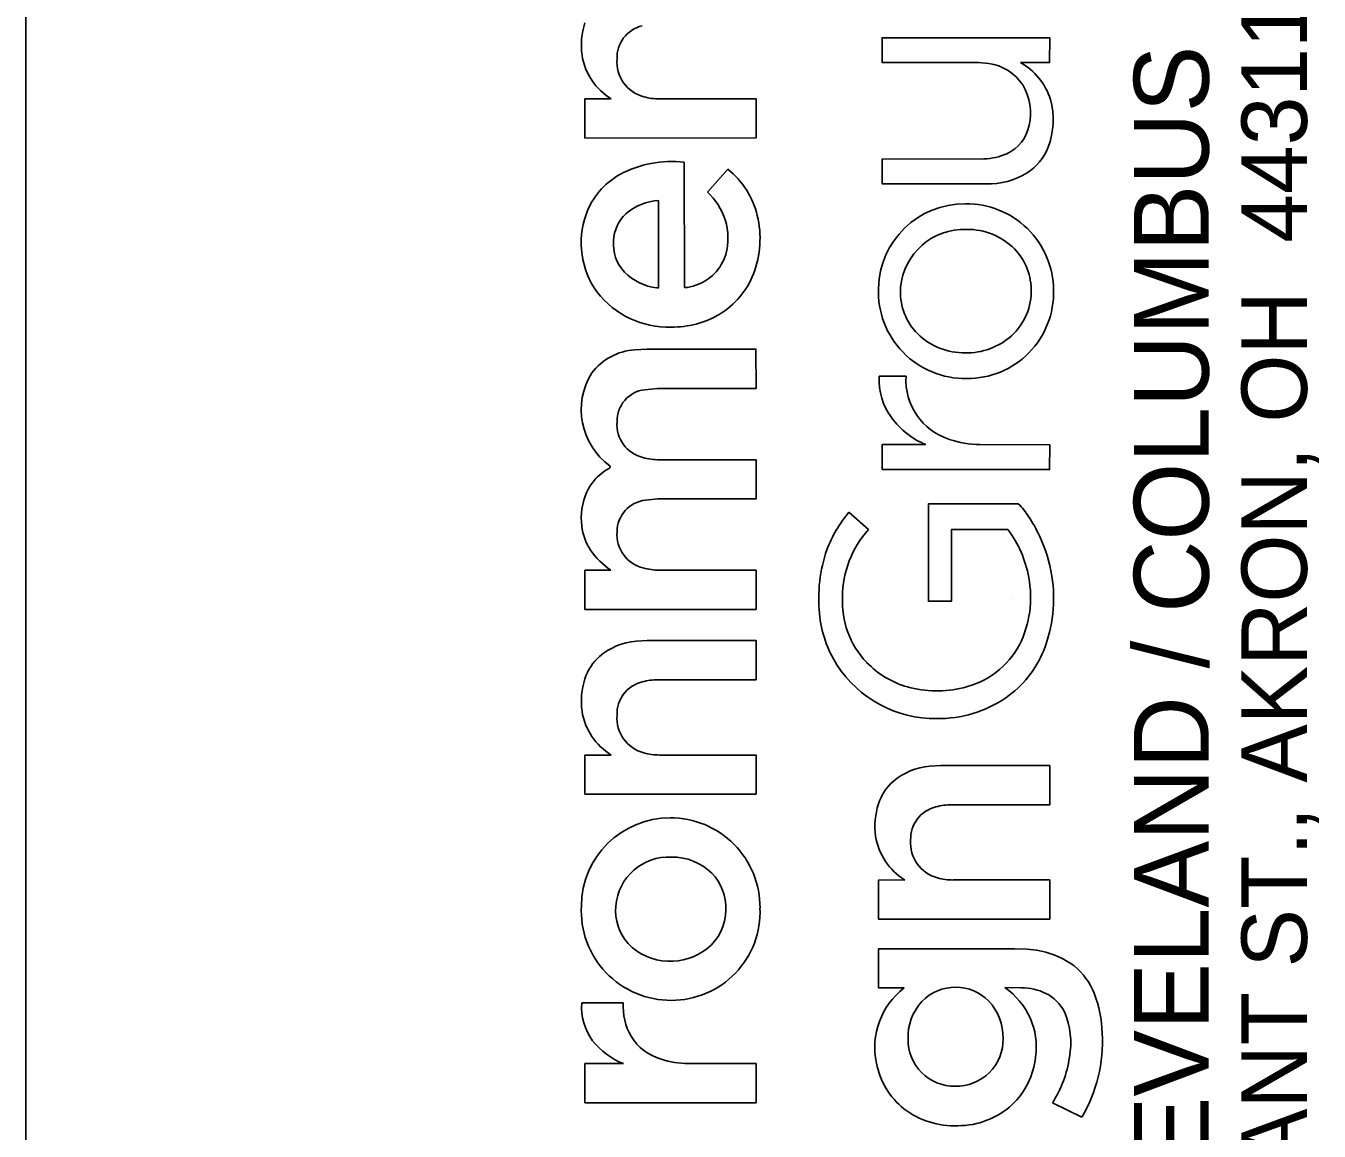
# Model space of a CAD drawing. Extents: x -6.7 to 34, y -1.6 to 22.
# Drawn here: x 32 to 32.984, y 3.594 to 4.436 of the extents above; entities that cross this region are included whole.
import ezdxf

# ---------------------------------------------------------------- set-up
doc = ezdxf.new("R2010")
doc.units = 0
doc.layers.add('SH_Border', color=7, linetype='Continuous')
doc.layers.add('SH_Cut_Line', color=7, linetype='Continuous')

msp = doc.modelspace()

# ---------------------------------------------------------------- linework, layer by layer
at = {"layer": 'SH_Border'}
msp.add_line((32, 0.5), (32, 21.5), dxfattribs=at)
at = {"layer": 'SH_Cut_Line'}
for p, q in [((32.65152, 4.40801), (32.65153, 4.42672)), ((32.65153, 4.42672), (32.7791, 4.42664)), ((32.7791, 4.42664), (32.77908, 4.40796)), ((32.7249, 4.40796), (32.65152, 4.40801)), ((32.7328, 4.40727), (32.7249, 4.40796)), ((32.77908, 4.40796), (32.75689, 4.40796)), ((32.42542, 4.38016), (32.44552, 4.38021)), ((32.42542, 4.35035), (32.42542, 4.38016)), ((32.48222, 4.38021), (32.55569, 4.38021)), ((32.55569, 4.38021), (32.55571, 4.35045)), ((32.55571, 4.35045), (32.42542, 4.35035)), ((32.50108, 4.33209), (32.50118, 4.23657)), ((32.65154, 4.33443), (32.72905, 4.3345)), ((32.65165, 4.31543), (32.65154, 4.33443)), ((32.51882, 4.30927), (32.53422, 4.32662)), ((32.73073, 4.31543), (32.65165, 4.31543)), ((32.48144, 4.23644), (32.48144, 4.30296)), ((32.48016, 4.23628), (32.48144, 4.23644)), ((32.46329, 4.18915), (32.47259, 4.18968)), ((32.47259, 4.18968), (32.55557, 4.18968)), ((32.55557, 4.18968), (32.55571, 4.15982)), ((32.64932, 4.16907), (32.66978, 4.16907)), ((32.48058, 4.15981), (32.47102, 4.15881)), ((32.55571, 4.15982), (32.48058, 4.15981)), ((32.65152, 4.11699), (32.68476, 4.117)), ((32.65152, 4.098), (32.65152, 4.11699)), ((32.72605, 4.11703), (32.7791, 4.11696)), ((32.7791, 4.11696), (32.77903, 4.098)), ((32.48218, 4.10553), (32.55571, 4.10548)), ((32.55571, 4.10548), (32.55571, 4.07568)), ((32.44443, 4.09922), (32.44455, 4.10072)), ((32.77903, 4.098), (32.65152, 4.098)), ((32.4809, 4.07567), (32.47143, 4.07474)), ((32.55571, 4.07568), (32.4809, 4.07567)), ((32.62636, 4.06548), (32.64114, 4.05241)), ((32.6868, 4.07185), (32.75516, 4.07192)), ((32.6868, 3.99778), (32.6868, 4.07185)), ((32.70448, 4.05241), (32.70432, 3.99775)), ((32.74737, 4.05227), (32.70448, 4.05241)), ((32.42542, 3.99152), (32.42545, 4.02138)), ((32.42545, 4.02138), (32.44515, 4.02138)), ((32.48206, 4.02138), (32.55571, 4.02136)), ((32.55571, 4.02136), (32.55571, 3.99156)), ((32.70432, 3.99775), (32.6868, 3.99778)), ((32.75, 4), (32.75, 4)), ((32.55571, 3.99156), (32.42542, 3.99152)), ((32.46439, 3.96736), (32.47289, 3.96783)), ((32.47289, 3.96783), (32.55571, 3.96783)), ((32.55571, 3.96783), (32.55571, 3.93804)), ((32.55571, 3.93804), (32.4814, 3.93796)), ((32.42542, 3.88066), (32.44552, 3.88071)), ((32.42542, 3.85086), (32.42542, 3.88066)), ((32.48222, 3.88071), (32.55569, 3.88071)), ((32.55569, 3.88071), (32.55571, 3.85096)), ((32.68784, 3.8722), (32.69634, 3.87266)), ((32.69634, 3.87266), (32.77916, 3.87266)), ((32.77916, 3.87266), (32.77917, 3.84287)), ((32.55571, 3.85096), (32.42542, 3.85086)), ((32.77917, 3.84287), (32.70485, 3.8428)), ((32.64888, 3.7855), (32.66897, 3.78555)), ((32.64888, 3.75569), (32.64888, 3.7855)), ((32.70568, 3.78555), (32.77915, 3.78555)), ((32.77915, 3.78555), (32.77917, 3.75579)), ((32.77917, 3.75579), (32.64888, 3.75569)), ((32.6489, 3.70336), (32.64889, 3.73322)), ((32.64889, 3.73322), (32.75236, 3.73322)), ((32.75236, 3.73322), (32.76191, 3.73285)), ((32.66836, 3.70336), (32.6489, 3.70336)), ((32.75763, 3.70356), (32.74487, 3.70361)), ((32.42299, 3.69193), (32.45454, 3.69193)), ((32.42542, 3.64577), (32.45473, 3.64579)), ((32.42542, 3.61593), (32.42542, 3.64577)), ((32.50413, 3.64581), (32.55571, 3.64573)), ((32.55571, 3.64573), (32.55565, 3.61593)), ((32.55565, 3.61593), (32.42542, 3.61593)), ((32.8036, 3.60491), (32.7812, 3.61598))]:
    msp.add_line(p, q, dxfattribs=at)
for points in [[(32.7328, 4.40727), (32.7249, 4.40796), (32.65152, 4.40801), (32.65153, 4.42672), (32.7791, 4.42664), (32.77908, 4.40796), (32.75689, 4.40796)], [(32.42542, 4.35035), (32.42542, 4.38016), (32.44552, 4.38021)], [(32.48222, 4.38021), (32.55569, 4.38021), (32.55571, 4.35045), (32.42542, 4.35035)], [(32.50108, 4.33209), (32.50118, 4.23657)], [(32.73073, 4.31543), (32.65165, 4.31543), (32.65154, 4.33443), (32.72905, 4.3345)], [(32.51882, 4.30927), (32.53422, 4.32662)], [(32.48016, 4.23628), (32.48144, 4.23644), (32.48144, 4.30296)], [(32.46329, 4.18915), (32.47259, 4.18968), (32.55557, 4.18968), (32.55571, 4.15982), (32.48058, 4.15981), (32.47102, 4.15881)], [(32.64932, 4.16907), (32.66978, 4.16907)], [(32.72605, 4.11703), (32.7791, 4.11696), (32.77903, 4.098), (32.65152, 4.098)], [(32.65152, 4.098), (32.65152, 4.11699), (32.68476, 4.117)], [(32.48218, 4.10553), (32.55571, 4.10548), (32.55571, 4.07568), (32.4809, 4.07567), (32.47143, 4.07474)], [(32.44443, 4.09922), (32.44455, 4.10072)], [(32.62636, 4.06548), (32.64114, 4.05241)], [(32.74737, 4.05227), (32.70448, 4.05241), (32.70432, 3.99775), (32.6868, 3.99778), (32.6868, 4.07185), (32.75516, 4.07192)], [(32.42542, 3.99152), (32.42545, 4.02138), (32.44515, 4.02138)], [(32.48206, 4.02138), (32.55571, 4.02136), (32.55571, 3.99156), (32.42542, 3.99152)], [(32.46439, 3.96736), (32.47289, 3.96783), (32.55571, 3.96783), (32.55571, 3.93804), (32.4814, 3.93796)], [(32.42542, 3.85086), (32.42542, 3.88066), (32.44552, 3.88071)], [(32.48222, 3.88071), (32.55569, 3.88071), (32.55571, 3.85096), (32.42542, 3.85086)], [(32.68784, 3.8722), (32.69634, 3.87266), (32.77916, 3.87266), (32.77917, 3.84287), (32.70485, 3.8428)], [(32.64888, 3.75569), (32.64888, 3.7855), (32.66897, 3.78555)], [(32.70568, 3.78555), (32.77915, 3.78555), (32.77917, 3.75579), (32.64888, 3.75569)], [(32.66836, 3.70336), (32.6489, 3.70336), (32.64889, 3.73322), (32.75236, 3.73322), (32.76191, 3.73285)], [(32.75763, 3.70356), (32.74487, 3.70361)], [(32.42299, 3.69193), (32.45454, 3.69193)], [(32.50413, 3.64581), (32.55571, 3.64573), (32.55565, 3.61593), (32.42542, 3.61593)], [(32.42542, 3.61593), (32.42542, 3.64577), (32.45473, 3.64579)], [(32.8036, 3.60491), (32.7812, 3.61598)]]:
    msp.add_lwpolyline(points, dxfattribs=at)
for centre, radius, start, end in [((32.47872, 4.42108), 0.05602, 162.27398, 187.79173), ((32.47872, 4.42108), 0.05602, 162.27398, 187.79173), ((32.47482, 4.41155), 0.02498, 103.68683, 182.21395), ((32.47482, 4.41155), 0.02498, 103.68683, 182.21395), ((32.47027, 4.4209), 0.04763, 188.96462, 238.69865), ((32.47027, 4.4209), 0.04763, 188.96462, 238.69865), ((32.47735, 4.40846), 0.02757, 175.58441, 255.13816), ((32.47735, 4.40846), 0.02757, 175.58441, 255.13816), ((32.72711, 4.36998), 0.03772, 33.50082, 81.32954), ((32.72711, 4.36998), 0.03772, 33.50082, 81.32954), ((32.73239, 4.36485), 0.04959, 17.62209, 60.38974), ((32.73239, 4.36485), 0.04959, 17.62209, 60.38974), ((32.72414, 4.3695), 0.04048, 346.56179, 31.75389), ((32.72414, 4.3695), 0.04048, 346.56179, 31.75389), ((32.48183, 4.42235), 0.04215, 254.08913, 270.52838), ((32.48183, 4.42235), 0.04215, 254.08913, 270.52838), ((32.72343, 4.36415), 0.05838, 339.16197, 15.61485), ((32.72343, 4.36415), 0.05838, 339.16197, 15.61485), ((32.73371, 4.36616), 0.03042, 294.63214, 348.48625), ((32.73371, 4.36616), 0.03042, 294.63214, 348.48625), ((32.739, 4.35901), 0.04201, 303.10391, 338.15613), ((32.739, 4.35901), 0.04201, 303.10391, 338.15613), ((32.49176, 4.24874), 0.08387, 83.62118, 118.28448), ((32.49176, 4.24874), 0.08387, 83.62118, 118.28448), ((32.72747, 4.38081), 0.04633, 271.95199, 294.08943), ((32.72747, 4.38081), 0.04633, 271.95199, 294.08943), ((32.47894, 4.27368), 0.05583, 118.82935, 160.62242), ((32.47894, 4.27368), 0.05583, 118.82935, 160.62242), ((32.49399, 4.2763), 0.06443, 13.53275, 51.36266), ((32.49399, 4.2763), 0.06443, 13.53275, 51.36266), ((32.7321, 4.37256), 0.05715, 268.62699, 301.47779), ((32.7321, 4.37256), 0.05715, 268.62699, 301.47779), ((32.4844, 4.26071), 0.04236, 94.01311, 130.88062), ((32.4844, 4.26071), 0.04236, 94.01311, 130.88062), ((32.48033, 4.27018), 0.05485, 19.0387, 45.44322), ((32.48033, 4.27018), 0.05485, 19.0387, 45.44322), ((32.48697, 4.27074), 0.06438, 160.52138, 215.78155), ((32.48697, 4.27074), 0.06438, 160.52138, 215.78155), ((32.47703, 4.2709), 0.02985, 132.98553, 177.1802), ((32.47703, 4.2709), 0.02985, 132.98553, 177.1802), ((32.48289, 4.27384), 0.0758, 339.35431, 13.37708), ((32.48289, 4.27384), 0.0758, 339.35431, 13.37708), ((32.71435, 4.23484), 0.06552, 89.48213, 178.77752), ((32.71435, 4.23484), 0.06552, 89.48213, 178.77752), ((32.71582, 4.23414), 0.06623, 0.42265, 90.7613), ((32.71582, 4.23414), 0.06623, 0.42265, 90.7613), ((32.48724, 4.27433), 0.04701, 344.60723, 17.00675), ((32.48724, 4.27433), 0.04701, 344.60723, 17.00675), ((32.47824, 4.26966), 0.03114, 175.00138, 223.2876), ((32.47824, 4.26966), 0.03114, 175.00138, 223.2876), ((32.71397, 4.23244), 0.04846, 87.68827, 175.01696), ((32.71397, 4.23244), 0.04846, 87.68827, 175.01696), ((32.71659, 4.23036), 0.05052, 44.91202, 90.75914), ((32.71659, 4.23036), 0.05052, 44.91202, 90.75914), ((32.49895, 4.27177), 0.03504, 288.01084, 343.55364), ((32.49895, 4.27177), 0.03504, 288.01084, 343.55364), ((32.71955, 4.23452), 0.04549, 358.32279, 43.83486), ((32.71955, 4.23452), 0.04549, 358.32279, 43.83486), ((32.48546, 4.27826), 0.04232, 225.06454, 262.79701), ((32.48546, 4.27826), 0.04232, 225.06454, 262.79701), ((32.49548, 4.26982), 0.0626, 300.94393, 338.73223), ((32.49548, 4.26982), 0.0626, 300.94393, 338.73223), ((32.48908, 4.27516), 0.06872, 217.74341, 271.65606), ((32.48908, 4.27516), 0.06872, 217.74341, 271.65606), ((32.50129, 4.25678), 0.02021, 269.70042, 294.87295), ((32.50129, 4.25678), 0.02021, 269.70042, 294.87295), ((32.71483, 4.2334), 0.06606, 177.53728, 270.94524), ((32.71483, 4.2334), 0.06606, 177.53728, 270.94524), ((32.71085, 4.23311), 0.0453, 175.51467, 221.42047), ((32.71085, 4.23311), 0.0453, 175.51467, 221.42047), ((32.71671, 4.23271), 0.06536, 269.30834, 1.67905), ((32.71671, 4.23271), 0.06536, 269.30834, 1.67905), ((32.71931, 4.23374), 0.04572, 308.90382, 359.30947), ((32.71931, 4.23374), 0.04572, 308.90382, 359.30947), ((32.49204, 4.27702), 0.07055, 269.20529, 300.33566), ((32.49204, 4.27702), 0.07055, 269.20529, 300.33566), ((32.71399, 4.23734), 0.05046, 222.66255, 268.37331), ((32.71399, 4.23734), 0.05046, 222.66255, 268.37331), ((32.71567, 4.23859), 0.05178, 266.55312, 308.67253), ((32.71567, 4.23859), 0.05178, 266.55312, 308.67253), ((32.46638, 4.14404), 0.04521, 93.91118, 142.30723), ((32.46638, 4.14404), 0.04521, 93.91118, 142.30723), ((32.47585, 4.14373), 0.05319, 148.28793, 233.9556), ((32.47585, 4.14373), 0.05319, 148.28793, 233.9556), ((32.69878, 4.16662), 0.04952, 177.16211, 216.28024), ((32.69878, 4.16662), 0.04952, 177.16211, 216.28024), ((32.71735, 4.16638), 0.04764, 176.76988, 252.15044), ((32.71735, 4.16638), 0.04764, 176.76988, 252.15044), ((32.47384, 4.13499), 0.02399, 96.75763, 181.6251), ((32.47384, 4.13499), 0.02399, 96.75763, 181.6251), ((32.47577, 4.13241), 0.02597, 175.81573, 256.16716), ((32.47577, 4.13241), 0.02597, 175.81573, 256.16716), ((32.70975, 4.17555), 0.06366, 216.91526, 246.88619), ((32.70975, 4.17555), 0.06366, 216.91526, 246.88619), ((32.7269, 4.19175), 0.07473, 251.13884, 269.34694), ((32.7269, 4.19175), 0.07473, 251.13884, 269.34694), ((32.4817, 4.15053), 0.04501, 254.34629, 270.61033), ((32.4817, 4.15053), 0.04501, 254.34629, 270.61033), ((32.4638, 4.06267), 0.04137, 117.91625, 139.24296), ((32.4638, 4.06267), 0.04137, 117.91625, 139.24296), ((32.46194, 4.06452), 0.03875, 139.52447, 154.84698), ((32.46194, 4.06452), 0.03875, 139.52447, 154.84698), ((32.47144, 4.0612), 0.04877, 156.06382, 187.3493), ((32.47144, 4.0612), 0.04877, 156.06382, 187.3493), ((32.47421, 4.05056), 0.02434, 96.5532, 179.94902), ((32.47421, 4.05056), 0.02434, 96.5532, 179.94902), ((32.70163, 4.00187), 0.09855, 139.79476, 159.13696), ((32.70163, 4.00187), 0.09855, 139.79476, 159.13696), ((32.72498, 4.03937), 0.04438, 30.98913, 47.16099), ((32.72498, 4.03937), 0.04438, 30.98913, 47.16099), ((32.46461, 4.05974), 0.04181, 186.5579, 213.38846), ((32.46461, 4.05974), 0.04181, 186.5579, 213.38846), ((32.67091, 4.00018), 0.11106, 25.30315, 33.96179), ((32.67091, 4.00018), 0.11106, 25.30315, 33.96179), ((32.47608, 4.04863), 0.02628, 175.722, 255.78627), ((32.47608, 4.04863), 0.02628, 175.722, 255.78627), ((32.69899, 4.00079), 0.07753, 138.25804, 179.70064), ((32.69899, 4.00079), 0.07753, 138.25804, 179.70064), ((32.67889, 4.00099), 0.08556, 10.07509, 36.83189), ((32.67889, 4.00099), 0.08556, 10.07509, 36.83189), ((32.6704, 3.99987), 0.11166, 8.80339, 25.33484), ((32.6704, 3.99987), 0.11166, 8.80339, 25.33484), ((32.47886, 4.07078), 0.0598, 214.70433, 235.68724), ((32.47886, 4.07078), 0.0598, 214.70433, 235.68724), ((32.7187, 3.99968), 0.11536, 161.14379, 185.62812), ((32.7187, 3.99968), 0.11536, 161.14379, 185.62812), ((32.48195, 4.06518), 0.0438, 253.66719, 270.14979), ((32.48195, 4.06518), 0.0438, 253.66719, 270.14979), ((32.68425, 4.00057), 0.08036, 333.46689, 11.03668), ((32.68425, 4.00057), 0.08036, 333.46689, 11.03668), ((32.67564, 3.99977), 0.10649, 338.28866, 9.28548), ((32.67564, 3.99977), 0.10649, 338.28866, 9.28548), ((32.68811, 3.99732), 0.06676, 176.66577, 223.6912), ((32.68811, 3.99732), 0.06676, 176.66577, 223.6912), ((32.69336, 3.99699), 0.08987, 185.50773, 212.01294), ((32.69336, 3.99699), 0.08987, 185.50773, 212.01294), ((32.46871, 3.91767), 0.04988, 94.97056, 130.22484), ((32.46871, 3.91767), 0.04988, 94.97056, 130.22484), ((32.69868, 3.99547), 0.0652, 282.88151, 331.81475), ((32.69868, 3.99547), 0.0652, 282.88151, 331.81475), ((32.69835, 3.99168), 0.08241, 305.03061, 337.67573), ((32.69835, 3.99168), 0.08241, 305.03061, 337.67573), ((32.46348, 3.92602), 0.04016, 132.22383, 161.68229), ((32.46348, 3.92602), 0.04016, 132.22383, 161.68229), ((32.69211, 3.99748), 0.08908, 212.70222, 270.71399), ((32.69211, 3.99748), 0.08908, 212.70222, 270.71399), ((32.69045, 4.00011), 0.07039, 224.02147, 253.88), ((32.69045, 4.00011), 0.07039, 224.02147, 253.88), ((32.47872, 3.92158), 0.05602, 162.27398, 187.79173), ((32.47872, 3.92158), 0.05602, 162.27398, 187.79173), ((32.48108, 3.89196), 0.04601, 89.60515, 105.33026), ((32.48108, 3.89196), 0.04601, 89.60515, 105.33026), ((32.47482, 3.91206), 0.02498, 103.68683, 182.21395), ((32.47482, 3.91206), 0.02498, 103.68683, 182.21395), ((32.69318, 4.01254), 0.08309, 254.45353, 283.9512), ((32.69318, 4.01254), 0.08309, 254.45353, 283.9512), ((32.69429, 3.99979), 0.09138, 269.3273, 304.19632), ((32.69429, 3.99979), 0.09138, 269.3273, 304.19632), ((32.47027, 3.92141), 0.04763, 188.96462, 238.69865), ((32.47027, 3.92141), 0.04763, 188.96462, 238.69865), ((32.47735, 3.90897), 0.02757, 175.58441, 255.13816), ((32.47735, 3.90897), 0.02757, 175.58441, 255.13816), ((32.48183, 3.92286), 0.04215, 254.08913, 270.52838), ((32.48183, 3.92286), 0.04215, 254.08913, 270.52838), ((32.69216, 3.82251), 0.04988, 94.97056, 130.22484), ((32.69216, 3.82251), 0.04988, 94.97056, 130.22484), ((32.68694, 3.83085), 0.04016, 132.22383, 161.68229), ((32.68694, 3.83085), 0.04016, 132.22383, 161.68229), ((32.70217, 3.82642), 0.05602, 162.27398, 187.79173), ((32.70217, 3.82642), 0.05602, 162.27398, 187.79173), ((32.69828, 3.81689), 0.02498, 103.68683, 182.21395), ((32.69828, 3.81689), 0.02498, 103.68683, 182.21395), ((32.70453, 3.79679), 0.04601, 89.60515, 105.33026), ((32.70453, 3.79679), 0.04601, 89.60515, 105.33026), ((32.49014, 3.76543), 0.0674, 89.84756, 179.64047), ((32.49014, 3.76543), 0.0674, 89.84756, 179.64047), ((32.49057, 3.76474), 0.0681, 359.54009, 90.21138), ((32.49057, 3.76474), 0.0681, 359.54009, 90.21138), ((32.69372, 3.82624), 0.04763, 188.96462, 238.69865), ((32.69372, 3.82624), 0.04763, 188.96462, 238.69865), ((32.7008, 3.81381), 0.02757, 175.58441, 255.13816), ((32.7008, 3.81381), 0.02757, 175.58441, 255.13816), ((32.48923, 3.76263), 0.0404, 87.04809, 175.57259), ((32.48923, 3.76263), 0.0404, 87.04809, 175.57259), ((32.49204, 3.75999), 0.04299, 45.84264, 90.98008), ((32.49204, 3.75999), 0.04299, 45.84264, 90.98008), ((32.49458, 3.76421), 0.03821, 357.88569, 44.15902), ((32.49458, 3.76421), 0.03821, 357.88569, 44.15902), ((32.70529, 3.82769), 0.04215, 254.08913, 270.52838), ((32.70529, 3.82769), 0.04215, 254.08913, 270.52838), ((32.49083, 3.76209), 0.06819, 176.8344, 270.40384), ((32.49083, 3.76209), 0.06819, 176.8344, 270.40384), ((32.48729, 3.7625), 0.03848, 175.15378, 221.14706), ((32.48729, 3.7625), 0.03848, 175.15378, 221.14706), ((32.49123, 3.76139), 0.06749, 270.06243, 2.37759), ((32.49123, 3.76139), 0.06749, 270.06243, 2.37759), ((32.49446, 3.76318), 0.0383, 308.28936, 359.43468), ((32.49446, 3.76318), 0.0383, 308.28936, 359.43468), ((32.48919, 3.76607), 0.04228, 223.09994, 268.80895), ((32.48919, 3.76607), 0.04228, 223.09994, 268.80895), ((32.49096, 3.7679), 0.04418, 266.56515, 308.06078), ((32.49096, 3.7679), 0.04418, 266.56515, 308.06078), ((32.75907, 3.66789), 0.06503, 53.40344, 87.49062), ((32.75907, 3.66789), 0.06503, 53.40344, 87.49062), ((32.76517, 3.68039), 0.05141, 21.60748, 50.5577), ((32.76517, 3.68039), 0.05141, 21.60748, 50.5577), ((32.70292, 3.65813), 0.05692, 127.37482, 192.22468), ((32.70292, 3.65813), 0.05692, 127.37482, 192.22468), ((32.70693, 3.66927), 0.0346, 88.47302, 136.42562), ((32.70693, 3.66927), 0.0346, 88.47302, 136.42562), ((32.70814, 3.66963), 0.03424, 44.27195, 90.47623), ((32.70814, 3.66963), 0.03424, 44.27195, 90.47623), ((32.71421, 3.65829), 0.05472, 352.1125, 55.92295), ((32.71421, 3.65829), 0.05472, 352.1125, 55.92295), ((32.75666, 3.65725), 0.04633, 65.01687, 88.8011), ((32.75666, 3.65725), 0.04633, 65.01687, 88.8011), ((32.46616, 3.68882), 0.04329, 175.87313, 216.34747), ((32.46616, 3.68882), 0.04329, 175.87313, 216.34747), ((32.50087, 3.68948), 0.04639, 176.9688, 209.60636), ((32.50087, 3.68948), 0.04639, 176.9688, 209.60636), ((32.71141, 3.66602), 0.0401, 137.46739, 182.33237), ((32.71141, 3.66602), 0.0401, 137.46739, 182.33237), ((32.70368, 3.666), 0.03996, 358.57141, 43.53765), ((32.70368, 3.666), 0.03996, 358.57141, 43.53765), ((32.7626, 3.67155), 0.03085, 26.26808, 63.80301), ((32.7626, 3.67155), 0.03085, 26.26808, 63.80301), ((32.73069, 3.66714), 0.08835, 1.15143, 21.3627), ((32.73069, 3.66714), 0.08835, 1.15143, 21.3627), ((32.73565, 3.66154), 0.05953, 349.30734, 23.43071), ((32.73565, 3.66154), 0.05953, 349.30734, 23.43071), ((32.47466, 3.69716), 0.05511, 218.09809, 248.7907), ((32.47466, 3.69716), 0.05511, 218.09809, 248.7907), ((32.49514, 3.68814), 0.04079, 211.94466, 253.2028), ((32.49514, 3.68814), 0.04079, 211.94466, 253.2028), ((32.70645, 3.6637), 0.03511, 178.88208, 271.08374), ((32.70645, 3.6637), 0.03511, 178.88208, 271.08374), ((32.70818, 3.66404), 0.03546, 268.27882, 1.55016), ((32.70818, 3.66404), 0.03546, 268.27882, 1.55016), ((32.70538, 3.66244), 0.11383, 329.6388, 3.25998), ((32.70538, 3.66244), 0.11383, 329.6388, 3.25998), ((32.50465, 3.7165), 0.07069, 252.46555, 269.57296), ((32.50465, 3.7165), 0.07069, 252.46555, 269.57296), ((32.70463, 3.65696), 0.05837, 190.75182, 231.28919), ((32.70463, 3.65696), 0.05837, 190.75182, 231.28919), ((32.70988, 3.65708), 0.05887, 313.74196, 353.8554), ((32.70988, 3.65708), 0.05887, 313.74196, 353.8554), ((32.70738, 3.66334), 0.08771, 327.31495, 351.57478), ((32.70738, 3.66334), 0.08771, 327.31495, 351.57478), ((32.70954, 3.65901), 0.06051, 269.6361, 312.70877), ((32.70954, 3.65901), 0.06051, 269.6361, 312.70877), ((32.70632, 3.66112), 0.06269, 232.46061, 272.59022), ((32.70632, 3.66112), 0.06269, 232.46061, 272.59022)]:
    msp.add_arc(centre, radius, start, end, dxfattribs=at)

# ---------------------------------------------------------------- texts
for s, height, p in [('450 GRANT ST., AKRON, OH  44311', 0.0498462, (32.97489, 3.33738)), ('AKRON / CLEVELAND / COLUMBUS', 0.056969, (32.90012, 3.138))]:
    msp.add_text(s, height=height, rotation=90, dxfattribs=at).set_placement(p)

doc.saveas('drawing.dxf')
